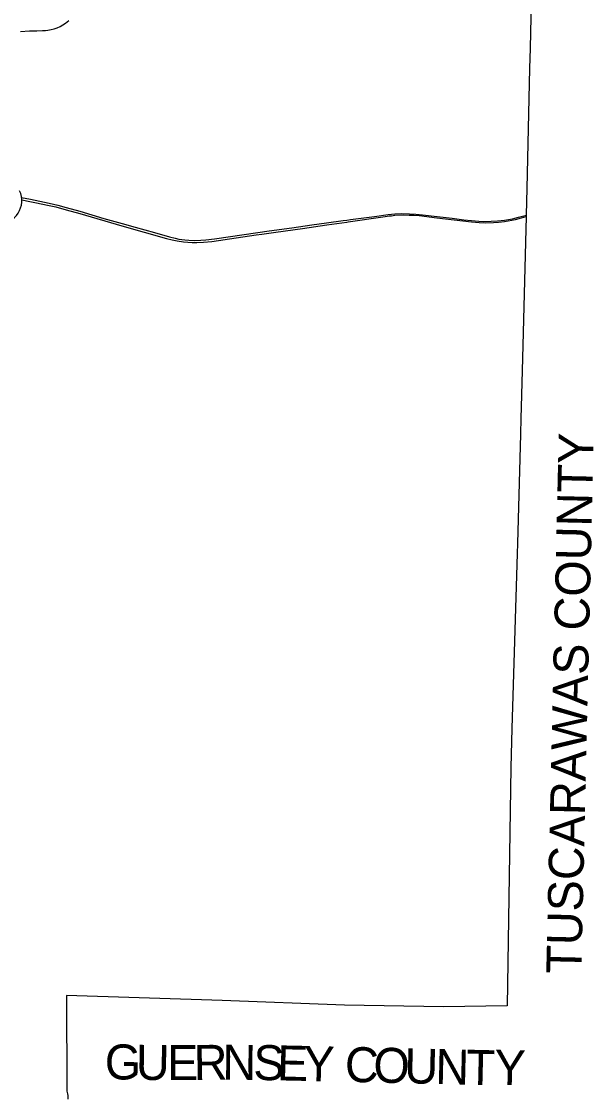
# Model space of a CAD drawing. Extents: x 2004415 to 2276415, y 751181 to 927181.
# Drawn here: x 2199651 to 2215983, y 807649 to 838414 of the extents above; entities that cross this region are included whole.
import ezdxf

# ---------------------------------------------------------------- set-up
doc = ezdxf.new("R2010")
doc.units = 0
for name, color, linetype in [('GM_X_County', 7, 'Continuous'), ('GM_X_County_Text', 7, 'Continuous'), ('GM_X_State_Route', 7, 'Continuous'), ('GM_X_US_Shield', 7, 'Continuous'), ('UT_P_Electric', 7, 'Continuous')]:
    doc.layers.add(name, color=color, linetype=linetype)

msp = doc.modelspace()

# ---------------------------------------------------------------- linework, layer by layer
at = {"layer": 'GM_X_County'}
msp.add_lwpolyline([(2214279, 842459), (2214173, 837662), (2214172, 837654), (2214160, 837073), (2214085, 833645), (2214066, 832888), (2214065, 832847), (2213957, 828794), (2213920, 827395), (2213912, 827086), (2213899, 826623), (2213880, 825927), (2213814, 823506), (2213806, 823219), (2213725, 820716), (2213655, 818221), (2213626, 817104), (2213518, 810296), (2211703, 810263), (2208876, 810317), (2205381, 810448), (2200936, 810586), (2200946, 807855), (2200966, 807785), (2200976, 807730), (2200976, 807629)], dxfattribs=at)
at = {"layer": 'GM_X_State_Route'}
msp.add_lwpolyline([(2199623, 838132), (2199874, 838146), (2200091, 838151), (2200247, 838157), (2200332, 838161), (2200405, 838171), (2200496, 838184), (2200581, 838210), (2200668, 838237), (2200749, 838272), (2200831, 838319), (2200908, 838368), (2201005, 838441)], dxfattribs=at)
at = {"layer": 'GM_X_US_Shield'}
msp.add_arc((2199004, 833297), 654, 269.3617, 25.1681, dxfattribs=at)
at = {"layer": 'UT_P_Electric'}
for points in [[(2199651, 833389), (2199903, 833339), (2200439, 833225), (2200691, 833164), (2200923, 833102), (2201311, 832995), (2201997, 832792), (2202526, 832645), (2202898, 832538), (2203445, 832383), (2203872, 832261), (2204041, 832221), (2204147, 832199), (2204310, 832178), (2204426, 832167), (2204583, 832162), (2204766, 832166), (2204915, 832178), (2205162, 832209), (2205617, 832274), (2206724, 832432), (2207371, 832524), (2207941, 832604), (2208364, 832665), (2208840, 832730), (2208938, 832743)], [(2199657, 833322), (2199887, 833276), (2200075, 833239), (2200392, 833172), (2200630, 833116), (2200926, 833037), (2201311, 832928), (2202519, 832582), (2203790, 832218), (2203953, 832175), (2204091, 832147), (2204273, 832119), (2204399, 832107), (2204520, 832100), (2204659, 832100), (2204851, 832108), (2205085, 832135), (2205784, 832237), (2206352, 832317), (2206515, 832340), (2206914, 832395), (2207677, 832504), (2208367, 832602), (2208941, 832684)], [(2208938, 832743), (2209042, 832757), (2209728, 832847), (2210118, 832899), (2210314, 832917), (2210511, 832927), (2210732, 832925), (2210913, 832914), (2211101, 832895), (2211520, 832843), (2211944, 832793), (2212277, 832753), (2212503, 832726), (2212707, 832710), (2212856, 832704), (2213065, 832709), (2213240, 832719), (2213444, 832742), (2213674, 832782), (2213845, 832821), (2214067, 832885)], [(2208941, 832684), (2208977, 832689), (2210036, 832844)], [(2210036, 832844), (2210150, 832860), (2210213, 832868), (2210309, 832879), (2210545, 832888), (2210721, 832884), (2210861, 832879), (2211006, 832869), (2211511, 832806), (2212500, 832688), (2212717, 832669), (2212899, 832668), (2213125, 832672), (2213270, 832684), (2213446, 832703), (2213552, 832722), (2213752, 832759), (2213932, 832805), (2214066, 832844)]]:
    msp.add_lwpolyline(points, dxfattribs=at)

# ---------------------------------------------------------------- texts
at = {"layer": 'GM_X_County_Text'}
for s, rotation, p in [('TUSCARAWAS COUNTY', 88.6727, (2215634, 811202)), ('G', 358.8201, (2202018, 808203)), ('U', 359.1885, (2202909, 808184)), ('E', 0.1879, (2203812, 808172)), ('R', 0.9417, (2204575, 808174)), ('N', 359.4857, (2205382, 808188)), ('S', 359.0235, (2206264, 808180)), ('E', 358.7708, (2206940, 808168)), ('Y', 358.683, (2207688, 808152)), ('C', 358.6613, (2208875, 808125)), ('O', 358.6602, (2209689, 808106)), ('U', 358.6613, (2210573, 808085)), ('N', 358.6602, (2211458, 808064)), ('T', 358.6603, (2212342, 808044)), ('Y', 358.6603, (2213143, 808044))]:
    msp.add_text(s, height=1000, rotation=rotation, dxfattribs=at).set_placement(p)

doc.saveas('drawing.dxf')
